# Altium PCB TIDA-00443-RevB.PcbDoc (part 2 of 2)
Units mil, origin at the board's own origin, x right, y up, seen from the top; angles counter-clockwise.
Board outline 5881 x 3685.61 mil, 2 copper layers (Top Layer, Bottom Layer), stack 62 mil thick; 123 components, 50 nets, 265 pads, 37 vias.
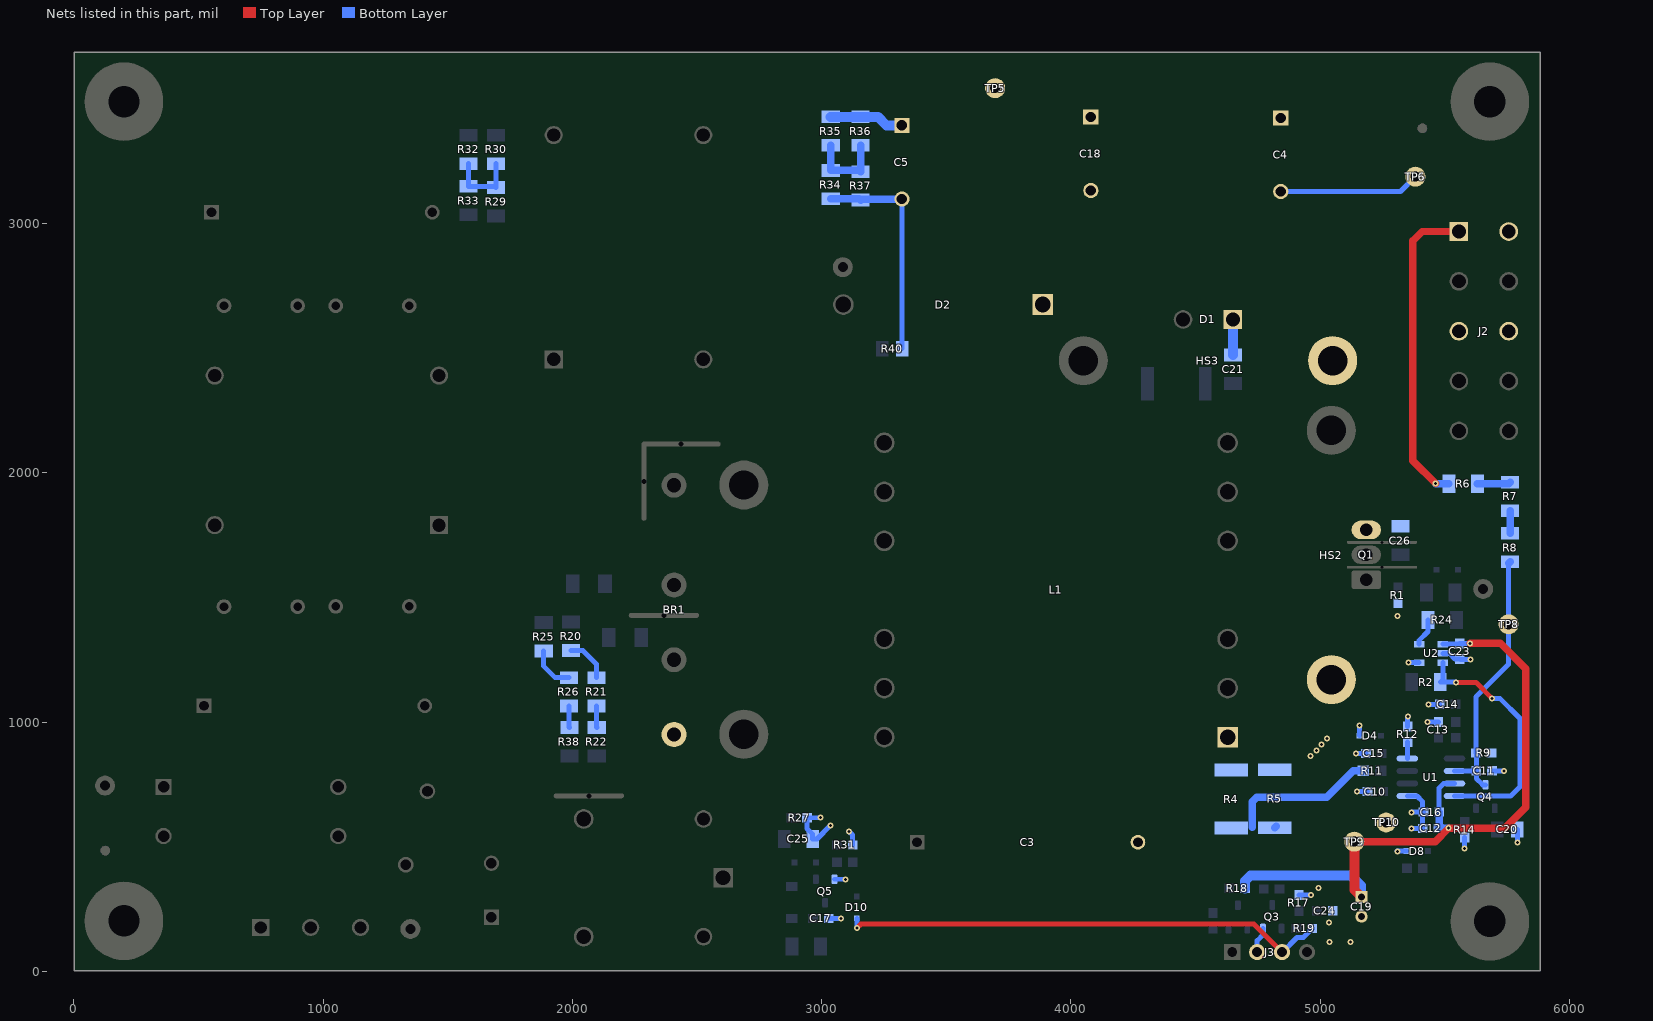
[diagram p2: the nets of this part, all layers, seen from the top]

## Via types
v1: diameter 24, hole 12, Top Layer to Bottom Layer, tented both sides, 37 vias

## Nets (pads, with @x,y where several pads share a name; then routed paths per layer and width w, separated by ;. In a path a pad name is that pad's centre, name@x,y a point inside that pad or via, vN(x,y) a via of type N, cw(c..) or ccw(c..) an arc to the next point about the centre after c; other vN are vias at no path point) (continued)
NetR2_1: R2.1 U1.8 U2.3 | length 1014
  Top Layer w20: v1(5545,1159) 5625,1159 v1(5689,1095)
  Bottom Layer w20: U2.3@5491.99,1237.98 5491.99,1169.89 R2.1@5482.08,1159.98 5544.02,1159.98 v1(5545,1159) ; U1.8@5538.99,703.5 5764.5,703.5 5802,741 5802,1014 5721,1095 v1(5689,1095)
NetR6_1: R6.1 R7.2 | length 133.4
  Bottom Layer w30: R6.1@5631.09,1956 5755.91,1956 R7.2@5762,1962.09
NetR7_1: R7.1 R8.2 | length 90.8
  Bottom Layer w30: R8.2@5762,1757.09 R7.1@5762,1847.91
NetR12_1: R12.1 U1.4 | length 66.4
  Bottom Layer w20: U1.4@5350.02,853.5 5350.02,918.51 R12.1@5350.99,919.48
NetR20_1: R20.1 R21.1 | length 178.7
  Bottom Layer w20: R20.1@1995,1286.91 2042.09,1286.91 2097,1232 R21.1@2097,1178.09
NetR21_2: R21.2 R22.2 | length 86.2
  Bottom Layer w20: R21.2@2097,1063.91 2097,979.09 R22.2@2098,978.09
NetR24_2: R24.2 U2.5 | length 111.9
  Bottom Layer w20: U2.5@5397.5,1312.78 5397.5,1327.5 5432.9,1362.9 R24.2@5432.9,1409.98
NetR25_1: R25.1 R26.1 | length 180.9
  Bottom Layer w20: R25.1@1885,1284.91 1885,1224 1930.91,1178.09 R26.1@1986,1178.09
NetR26_2: R26.2 R38.1 | length 86.7
  Bottom Layer w20: R26.2@1986,1063.91 1986,980.09 R38.1@1988,978.09
NetR29_1: R29.1 R30.2 R32.2 R33.1 | length 298.7
  Bottom Layer w20: R32.2@1583.64,3239.97 R33.1@1583.64,3149.14 1688.64,3149.14 R29.1@1693.64,3144.14 R30.2@1693.64,3239.97
NetR34_2: R34.2 R35.1 R36.1 R37.2 | length 328.7
  Bottom Layer w30: R35.1@3036.36,3313.97 R34.2@3036.36,3213.14 3151.36,3213.14 R37.2@3156.36,3208.14 R36.1@3156.36,3313.97
PFC_ON: D10.2 J3.3 R19.1 | length 1960.9
  Top Layer w20: v1(3141,173) 3158,190 4734,190 J3.3@4846.98,77.03
  Bottom Layer w20: v1(3141,173) D10.2@3141,212.69 ; J3.3@4846.98,77.03 4849,77.03 4907.27,135.3 4932.64,135.3 4968.5,171.15 R19.1@4968.5,172
PGND: C4.2 C5.2 C10.2 C11.2 C12.2 C13.1 C14.2 C15.1 C16.2 C17.2 C18.2 C19.2 C20.2 C23.2 C24.2 C25.2 C26.2 D4.2 D8.1 HS2.2 HS3.2 J2.3 J3.2 L1.1 Q1.3 Q3.2 Q5.2 R1.2 R4.1 R5.1 R9.1 R12.2 R14.2 R17.1 R27.1 R31.1 R34.1 R37.1 R40.1 TP6.1 TP10.1 U1.1 U2.2 U2.4 | length 2879.1
  Bottom Layer w20: v1(2995,617) 2994,616 R27.1@2941.5,616 2941.5,572.5 2964.09,549.91 C25.2@2964.09,531 2981,531 v1(3035,585) ; C17.2@3028.5,212 v1(3078,212) ; Q5.2@3051.4,369.24 3094.76,369.24 v1(3095,369) ; v1(3110,561) 3124.5,546.5 R31.1@3124.5,507 ; R37.1@3151.36,3098.97 R37.1@3156.36,3093.97 ; R40.1@3322,2498 C5.2@3322,3098.36 ; J3.2@4746.98,77.03 4746.98,122.98 4770.6,146.6 Q3.2@4770.6,171.76 ; C4.2@4842,3128.36 5322.36,3128.36 TP6.1@5382,3188 ; R17.1@4915,305.5 4963.5,305.5 v1(4964,306) ; v1(5143,874) 5147,874 C15.1@5183.49,873.98 ; v1(5148,722) 5150,722 5151.02,720.98 C10.2@5189.49,720.98 ; D4.2@5157.68,944.98 5157.68,985.68 v1(5158,986) ; v1(5310,481) 5309,482 D8.1@5346.69,482 ; U1.1@5350.02,703.5 5388.5,703.5 5411.5,680.5 C16.2@5411.5,639 ; R12.2@5350.99,982.47 5350.99,1021.99 v1(5352,1023) ; v1(5355,1238) 5360,1238 U2.4@5397.5,1237.98 ; v1@5365,573 v1(5366,573) C12.2@5411.5,573 C16.2@5411.5,639 ; v1(5367,638) 5368,639 C16.2@5411.5,639 ; C16.2@5414.5,639 C16.2@5411.5,639 ; v1(5431,1000) 5437,1000 C13.1@5474.5,999.99 ; v1(5434,1070) 5434.98,1070.98 C14.2@5479.49,1070.98 ; U2.2@5491.99,1275.38 5517.62,1275.38 5540.52,1252.48 C23.2@5559.99,1252.48 5562.49,1249.98 5596.98,1249.98 v1(5604,1250) ; v1(5579,492) 5580,492 R14.2@5580,536.5 ; C11.2@5689.5,804 v1(5737,804) ; v1(5791,517) C20.2@5791,569
  Bottom Layer w30: R34.1@3036.36,3098.97 R37.1@3151.36,3098.97 ; R37.1@3156.36,3093.97 3160.76,3098.36 C5.2@3322,3098.36
  other v1: 5037,118 5122,118 5036,195 4993,335 4962,864 4985,886 5006,909 5027,933 5310,1425
RTN: BR1.4 C3.2 R4.2 R5.2 R11.1 | length 606.8
  Bottom Layer w30: 4728,577 4728,681 4745,698 5026,698 5131.98,803.98 R11.1@5172.56,803.98 ; R5.2@4818,575.86 R5.2@4823.14,581
VCC: C12.1 C16.1 C19.1 C23.1 R18.2 TP9.1 U1.7 U2.1 | length 2756.3
  Top Layer w30: TP9.1@5137,520 5461,520 v1(5515,574) 5740,574 5825,659 5825,1214 5723.53,1315.47 v1(5601.47,1315.47)
  Top Layer w40: TP9.1@5137,520 5138,519 5138,326.37 C19.1@5166,298.37
  Bottom Layer w20: C16.1@5477.5,639 5477.5,735.5 5495.5,753.5 U1.7@5538.99,753.5 ; U2.1@5491.99,1312.78 5557.3,1312.78 C23.1@5559.99,1315.47 v1(5601.47,1315.47)
  Bottom Layer w30: C16.1@5477.5,639 5477.5,576 C12.1@5474.5,573 5514,573 v1(5515,574)
  Bottom Layer w40: R18.2@4698.5,333 4698.5,362.5 4720,384 5123,384 5163,344 5163,295.37 C19.1@5166,298.37
VDCBUS: C4.1 C5.1 C18.1 C21.1 D1.1 D2.1 J2.1 R6.2 R35.2 R36.2 TP5.1 | length 1713.3
  Top Layer w30: v1(5463,1957) 5372,2048 5372,2930 5410,2968 J2.1@5556.61,2968
  Bottom Layer w30: v1(5463,1957) 5464,1956 R6.2@5516.91,1956
  Bottom Layer w40: R35.2@3036.36,3428.14 R36.2@3156.36,3428.14 3225.86,3428.14 3260.36,3393.64 C5.1@3322,3393.64 ; D1.1@4650,2615 4651,2614 C21.1@4651,2472.09 ; J2.1@5553.29,2964.68 J2.1@5556.61,2968
VSENSE: C11.1 Q4.3 R8.1 R9.2 TP8.1 U1.6 | length 1070.4
  Bottom Layer w20: U1.6@5538.99,803.5 5626,803.5 C11.1@5626.5,804 ; Q4.3@5663,748.24 5651.76,748.24 5626.5,773.5 C11.1@5626.5,804 ; TP8.1@5756,1392 R8.1@5756,1636.91 ; TP8.1@5762,1398 5755,1391 5755,1231 5624.5,1100.5 R9.2@5624.5,876 5626.5,874 C11.1@5626.5,804
  Bottom Layer w30: R8.1@5756,1636.91 R8.1@5762,1642.91
pads on no net: FID1.1 FID2.1 FID3.1 FID4.1 H1.0 H2.0 H3.0 H4.0 H7.1 H8.1 H10.1 HS1.2 HS2.1 HS3.1 J2.2 J2.4 J2.5 K1.4 L1.7 L1.8 L1.9 L1.10 L1.11 L1.12

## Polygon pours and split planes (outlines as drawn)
NetC1_2 on Bottom Layer "Top Layer-No Net 5" (solid, remove dead copper, pour order 49): 2100,650 2100,575 2075,550 1750,550 1725,525 1725,400 1700,375 1650,375 1625,400 1625,896 1495,1026 1297,1026 1250,1073 1250,1825 1300,1875 1575,1875 1625,1825 1625,1200 1813,1012 1813,698 1836,675 2075,675
NetBR1_3 on Bottom Layer "Bottom Layer-No Net 2" (solid, remove dead copper, pour order 55): 2225,1207 2234,1198 3057,1198 3090,1226 3090,2185 2895,2380 2895,2660 2687,2867 2687,3463 2675,3475 2432,3475 2418,3461 2418,2868 2425,2850 2700,2575 2700,2250 2850,2100 2850,1410 2818,1378 2245,1378 2225,1358
NetC2_2 on Bottom Layer "Top Layer-No Net 8" (solid, remove dead copper, pour order 52): 1577,2298 1602,2323 1602,2848 1612,2858 1652,2858 1662,2848 1662,2407 1676,2393 1948,2393 1965,2410 1965,3053 1936,3082 1336,3082 1302,3048 1302,2323 1327,2298
PGND on Bottom Layer "Top Layer-No Net 2" (solid, pour order 32): 5099,1742 5106,1735 5381,1735 5391,1745 5391,1934 5374,1951 5110,1951 5099,1940
NetF1_1 on Bottom Layer "Top Layer-No Net" (solid, remove dead copper, pour order 44): 776,96 787,107 787,268.82 599,455.68 599,723 545,777 307,777 251,721 251,521 617,155 617,113 634,96
GNDE on Bottom Layer "Bottom Layer-No Net 3" (solid, remove dead copper, pour order 56): 925,125 984,125 994,135 994,385 900,479 900,805 1080,985 1080,3415 905,3590 90,3590 75,3575 75,3415 105,3385 830,3385 865,3350 865,1035 725,895 725,509 908,326 908,142
NetC1_1 on Bottom Layer "Top Layer-No Net 9" (solid, remove dead copper, pour order 57): 450,1900 649,1900 675,1874 675,980 459,980 425,1014 425,1875
NetC2_1 on Bottom Layer "Bottom Layer-No Net 5" (solid, remove dead copper, pour order 58): 455,2300 670,2300 695,2325 695,3220 670,3245 455,3245 430,3220 430,2325 455,2300
PGND on Bottom Layer "Bottom Layer-No Net 10" (solid, remove dead copper, pour order 39): 5374,1876 5390,1892 5390,2492 5400,2502 5808,2502 5820,2514 5820,2623 5809,2634 5361,2634 5334,2661 5334.01,3123.99 5194,3264 3315,3264 3261,3210 3261,2897 3286,2872 4771,2872 4817,2826 4817,1886 4827,1876
PGND on Bottom Layer "Bottom Layer-No Net 11" (solid, remove dead copper, pour order 40): 5245,1879 5245,1746 5232,1733 5104,1733 5096,1725 5096,1323.36 5147,1272 5147,1119 5072,1044 5072,920 4930,778 4578,778 4564,792 4564,974 4571,981 4789,981 4797,989 4797,1878 4817,1898 5226,1898
RTN on Bottom Layer "Bottom Layer-No Net 8" (solid, remove dead copper, pour order 36): 2342.95,884.88 2368.95,858.88 2432.95,858.88 2523.95,766.88 3523.95,766.88 3821.49,482 4892,482 4895,485 4895,657 4887,665 4364.83,665 3968.95,1060.88 2364.95,1060.88 2342.95,1038.88
NetJ1_3 on Bottom Layer "Top Layer-No Net 1" (solid, remove dead copper, pour order 46): 1106,231 1106,119 1125,100 1400,100 1425,125 1425,300 1430,305 1435,305 1439,301 1439,136 1475,100 1725,100 1935,310 2640,310 2650,320 2650,441 2641,450 1900,450 1750,300 1650,300 1440,510 1300,510 1283,493 1283,269 1264,250 1125,250
NetBR1_2 on Bottom Layer "Bottom Layer-No Net 1" (solid, remove dead copper, pour order 54): 2499,1599 2499,1499 2474,1474 2124,1474 2099,1499 2100,2300 2115,2315 2402,2315 2412,2325 2412,2516 2425,2529 2559,2529 2571,2517 2571,2191 2560,2180 2275,2180 2260,2165 2260,1638 2274,1624 2474,1624
PGND on Bottom Layer "Top Layer-No Net 6" (solid, remove dead copper, pour order 42): 5843,1590 5851,1582 5851,449 5789,387 5529,387 5415,273 5415,30 5402,17 5400,19 3010,20 2812,20 2765,126 2765,549.39 2848.06,636 3180,636 3195,621 3195,424 3275,344 3275,310.15 3275,298 3275,292 3284,283 3320,283 4536,281 4642,387 4901,387 4955,441 4955,739.89 4971,756 4971,769 4935,805 4935,821 5023,910 5037,910 5069,878 5076,878 5127,929 5127,1029 5271,1173 5271,1573 5288,1590
VDCBUS on Top Layer "Bottom Layer-No Net 12" (solid, remove dead copper, pour order 33): 3992,2621 3992,2869 3839,3022 3839,3121 3791,3169 3688,3169 3626,3107 3626,2945 3836,2735 3836,2619 3853,2602 3973,2602
PGND on Top Layer "Top Layer-No Net" (solid, remove dead copper, pour order 31): 2396,764 3166,764 3190,740 3190,370 3301.24,258.76 4856.24,258.76 4880,235 4880,50 4870,40 2825,40 2805,60 2805,695 2780,720 2400,720 2385,735 2385,753
PGND on Top Layer "Top Layer-No Net 6" (solid, remove dead copper, pour order 41): 5838,1610 5846,1602 5846,469 5784,407 5524,407 5410,293 5410,50 5397,37 5395,39 3430,45 3385,115 3315,155 3345,175 3285,230 3250,300 3355,300 4531,301 4636,406 4894,406 4950,462 4950,877 5266,1193 5266,1593 5283,1610
NetC1_2 on Top Layer "Top Layer-No Net 5" (solid, remove dead copper, pour order 48): 2100,650 2100,575 2075,550 1750,550 1725,525 1725,400 1700,375 1650,375 1625,400 1625,896 1495,1026 1297,1026 1250,1073 1250,1825 1300,1875 1575,1875 1625,1825 1625,1200 1814,1011 1814,697 1836,675 2075,675
NetC2_2 on Top Layer "Top Layer-No Net 8" (solid, remove dead copper, pour order 51): 1576,2298 1601,2323 1601,2848 1611,2858 1651,2858 1661,2848 1661,2407 1675,2393 1947,2393 1964,2410 1964,3053 1935,3082 1335,3082 1301,3048 1301,2323 1326,2298
NetBR1_2 on Top Layer "Bottom Layer-No Net 1" (solid, remove dead copper, pour order 53): 2498,1600 2498,1500 2473,1475 2123,1475 2098,1500 2099,2301 2114,2316 2401,2316 2411,2326 2411,2541 2421,2551 2564,2551 2570,2545 2570,2192 2559,2181 2274,2181 2259,2166 2259,1639 2273,1625 2473,1625
NetC26_1 on Top Layer "Bottom Layer-No Net 9" (solid, remove dead copper, pour order 38): 5245,1646 5232,1633 4614,1632 4516,1730 4516,2124 4405,2235 4405,2648 4416,2659 4474,2659 4486,2647 4486,2448 4525,2409 4526,2409 4730,2205 4730,1890 4911,1709 5233,1709 5245,1697
VDCBUS on Top Layer "Top Layer-No Net 2" (solid, pour order 30): 4599,2575 4610,2564 4692,2564 4702,2574 4702,2878 4697,2883 4603,2883 4599,2879
NetF1_1 on Top Layer "Top Layer-No Net" (solid, remove dead copper, pour order 43): 775,100 794,119 794,349 629,513 629,753 616,766 291,766 250,725 250,525 600,175 600,118 618,100
NetC1_1 on Top Layer "Top Layer-No Net 3" (solid, remove dead copper, pour order 47): 1475,664 1461,650 1170,650 1159,639 1159,495 1139,475 837,475 817,495 817,890 807,900 450,900 425,925 425,1200 425,1850 425,1874 425,1875 450,1900 650,1900 675,1875 675,1188 703,1160 995,1160 1025,1130 1025,910 1059,876 1294,876 1306,864 1306,772 1316,762 1463,762 1475,750
NetC2_1 on Top Layer "Top Layer-No Net 7" (solid, remove dead copper, pour order 50): 455,2300 670,2300 695,2325 695,3220 705,3230 2010,3230 2025,3245 2025,3455 2005,3475 575,3475 430,3330 430,2325
VDCBUS on Top Layer "Bottom Layer-No Net" (solid, remove dead copper, pour order 37): 4689,2865 4710,2886 4710,3215 4759,3264 4925,3264 4981,3208 4981,2958 5042,2897 5807,2897 5826,2916 5826,3044 5805,3065 5271,3065 5263,3073 5263,3575 5221,3617 3263,3617 3247,3601 3247,3280 3263,3264 3597,3264 3626,3235 3626,2959 3720,2865
NetJ1_3 on Top Layer "Top Layer-No Net 1" (solid, remove dead copper, pour order 45): 1106,231 1106,119 1125,100 1400,100 1425,125 1425,300 1430,305 1435,305 1439,301 1439,136 1475,100 1725,100 1935,310 2658.58,310 2675,326.42 2675,425 2650,450 1900,450 1750,300 1650,300 1440,510 1300,510 1283,493 1283,269 1264,250 1125,250
NetBR1_1 on Top Layer "Bottom Layer-No Net 6" (solid, remove dead copper, pour order 34): 2363,2018 2349,2004 2349,1858 2472,1735 2575,1735 2644,1666 2644,1575 2691,1528 3299,1528 3320,1507 3320,485 3329,476 3411,476 3424,489 3424,571 3628,775 3628,1782 3586,1824 2615,1824 2562,1877 2562,2001 2545,2018
NetBR1_1 on Top Layer "Top Layer-No Net 4" (solid, remove dead copper, pour order 35): 3332,489 3336,485 3824,485 4080,741 4080,1081 4093,1094 4659,1094 4682,1117 4682,1424 4668,1438 4020,1438 3789,1207 3789,816 3738,765 3656,765 3443,552 3340,552 3332,544

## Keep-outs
Top Layer:
  circle w6: c4080,3132.36 r110
Keep-Out Layer:
  lines w10: 21,22 21,3665 ; 24,22 5859,22 5859,3665 24,3665

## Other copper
Top Layer:
  text ".Layer_Name" at 505,-1086.49 h60
Bottom Layer:
  text ".Layer_Name" at 505,-1086.49 h60

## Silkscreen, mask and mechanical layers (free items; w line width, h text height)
Top Overlay:
  circle w6: c5281,1537 r6.4
  circle w6: c4684,2711 r6.4
  circle w6: c2354,2078 r6.4
  circle w6: c4771,921 r6.4
  lines w6: 2221,1957 2242,1957 ; 2231,1943 2231,1971 ; 2324,844 2324,2056 2544,2056 2544,844 2324,844
  text "TIDA-00443-RevB" at 583,3540 h60
  text ".Layer_Name" at 505,-1086.49 h60
Bottom Overlay:
  circle w6: c5504,1343 r7.81
  circle w6: c5308,677 r5.83
  lines w6: 3011,178 3011,172 3020,163 3029,163 ; 3080,332 3082,332 3100,350 3108,350 ; 5440,952 5420,952 5407,965 5407,1006 ; 5407,1006 5401,1000 5413,1000 5407,1006
  text "R9" at 5696,918 h30
  text ".Layer_Name" at 505,-1086.49 h60
Top Paste:
  text ".Layer_Name" at 505,-1086.49 h60
Bottom Paste:
  text ".Layer_Name" at 505,-1086.49 h60
Top Solder:
  text ".Layer_Name" at 505,-1086.49 h60
  text ".Layer_Name" at 505,-1086.49 h60
Bottom Solder:
  text ".Layer_Name" at 505,-1086.49 h60
Drill Guide:
  text ".Layer_Name" at 505,-1086.49 h60
M1 Board Outline:
  the board outline again, w10
M2 Board Dimensions:
  rectangle: -72,-503 53,-378
  rectangle: 53,-628 428,-503
  lines w7: -72,-503 928,-503 ; 53,-628 53,-378 ; 178,-628 178,-378 ; 428,-628 428,-378 ; 678,-628 678,-378 ; -72,-628 928,-628 928,-378 -72,-378 -72,-628
M3 3D STEP Top:
  text ".Layer_Name" at 505,-1086.49 h60
M4 3D STEP Bottom:
  text ".Layer_Name" at 505,-1086.49 h60
M5 Assembly Top:
  circle w6: c2683.8,366 r10.2
  circle w6: c2396,2033 r10.77
  circle w6: c4613,114 r7.62
  circle w6: c5216,1503 r12.81
  circle w6: c4724,2653 r8
  circle w10: c1529,1789 r14.32
  lines w10: -364,-1158.17 6236,-1158.17 ; -364,-954.83 6238,-954.83 ; -364,-751.5 -364,-1361.5 3641,-1361.5 6238,-1361.5 6238,-751.5 -363.5,-751.5 -363.5,-1361.5 1212,-1361.5 ; 2101,-1361.5 2101,-751.5 ; 3368,-954.83 3368,-751.5 ; 4208,-954.83 4208,-751.5 ; 4830,-1368 4830,-1165.17
  text "COMPONENTS MARKED 'DNP' SHOULD NOT BE POPULATED." at 1081.5,-546.5 h30
  text "ASSEMBLY VARIANT:" at 1081,-662 h30
  text ".VariantName" at 2117,-662 h30
  text "PCB VIEWED FROM TOP SIDE" at -300.5,-883.67 h30
  text "BOARD #:" at 2176,-883.67 h30
  text ".PRJ_Number" at 2721.5,-883.67 h30
  text "REV:" at 3566,-883.67 h30
  text ".PCB_Rev" at 3857.5,-883.67 h30
  text "SVN REV:" at 4404,-883.67 h30
  text ".VersionControl_RevNumber" at 4910,-883.67 h30
  text ".layer_Name" at 486,-1076 h60
  text "PLOT NAME =" at -300.5,-1292.34 h30
  text ".plot_File_Name" at 505,-1292.34 h30
  text "GENERATED    :" at 2178,-1292.34 h30
  text ".Print_Date" at 3047.5,-1292.34 h30
  text ".Print_Time" at 3776.5,-1292.34 h30
  text "TEXAS INSTRUMENTS" at 5041,-1292.34 h30
M6 Assembly Bottom:
  circle w6: c5459,1314 r5.66
  circle w6: c5382,704 r7.07
  circle w6: c5704.29,694 r7.71
  circle w6: c4847,209 r7.81
  circle w6: c4710,209 r7.21
  circle w6: c2976.49,381 r5.51
  lines w10: -364.5,-955.33 6237.5,-955.33 ; -362.5,-1158.67 6237.5,-1158.67 ; 1043.5,-1368.5 1043.5,-1165.67 ; 1665.5,-955.33 1665.5,-752 ; 2505.5,-955.33 2505.5,-752 ; 3772.5,-1362 3772.5,-752 ; 4661.5,-1362 6237,-1362 6237,-752 -364.5,-752 -364.5,-1362 2232.5,-1362 6237.5,-1362 6237.5,-752
  text "COMPONENTS MARKED 'DNP' SHOULD NOT BE POPULATED." at 6030,-546 h30
  text ".VariantName" at 4986,-662 h30
  text "ASSEMBLY VARIANT:" at 6025,-662 h30
  text ".VersionControl_RevNumber" at 963.5,-884.17 h30
  text "SVN REV:" at 1469.5,-884.17 h30
  text ".PCB_Rev" at 2016,-884.17 h30
  text "REV:" at 2307.5,-884.17 h30
  text ".PRJ_Number" at 3152,-884.17 h30
  text "BOARD #:" at 3697.5,-884.17 h30
  text "PCB VIEWED FROM BOTTOM SIDE" at 6174,-884.17 h30
  text ".layer_Name" at 5892,-1089 h60
  text "TEXAS INSTRUMENTS" at 832.5,-1292.84 h30
  text ".Print_Time" at 2097,-1292.84 h30
  text ".Print_Date" at 2826,-1292.84 h30
  text "GENERATED    :" at 3695.5,-1292.84 h30
  text ".plot_File_Name" at 5368.5,-1292.84 h30
  text "PLOT NAME =" at 6174,-1292.84 h30
M9 Title Sheet:
  drawing of 57 lines, arcs and shapes, not listed
  text "1" at 667.84,7808.5 h70
  text "2" at 3163.5,7808.5 h70
  text "3" at 5652.84,7808.5 h70
  text "4" at 8159.51,7808.5 h70
  text "5" at 10658.5,7808.5 h70
  text "6" at 13163.5,7808.5 h70
  text "A" at -488.5,6665.5 h70
  text "A" at 14311.5,6665.5 h70
  text "B" at -488.5,4285.5 h70
  text "B" at 14311.5,4285.5 h70
  text "C" at -488.5,1910.5 h70
  text "C" at 14311.5,1910.5 h70
  text "PROJECT TITLE:" at 11271.5,49.5 h45
  text ".PRJ_Title" at 11363,-81 h70
  text "DESIGNED FOR:" at 11271.5,-251.5 h45
  text ".PRJ_Customer" at 11321.5,-391.5 h70
  text "D" at -488.5,-459.5 h70
  text "D" at 14311.5,-459.5 h70
  text "FILE NAME:" at 11271.5,-551.5 h45
  text ".PCB_File_Name_No_Path" at 11321.5,-671.5 h70
  text "Texas Instruments (TI) and/or its licensors do not warrant the accuracy or completeness of this specification" at 6302,-833.34 h45
  text "ENGINEER:" at 11271.5,-841.5 h45
  text "LAYOUT BY:" at 12776.5,-841.5 h45
  text "or any information contained therein. TI and/or its licensors do not warrant that this design will meet" at 6257.01,-946 h45
  text ".PRJ_Engineer" at 11321.5,-996.49 h70
  text ".pcb_Layout" at 12827,-996.49 h70
  text "the specifications, will be suitable for your application or fit for any particular purpose, or will operate in" at 6257.01,-1058.67 h45
  text "ALTIUM DESIGNER VERSION:" at 12776.5,-1151.5 h45
  text "an implementation. TI and/or its licensors do not warrant that the design is production worthy. You should" at 6257.01,-1171.33 h45
  text "completely validate and test your design implementation to confirm the system functionality for your application." at 6302,-1284 h45
  text ".print_Scale" at 11321.5,-1284.83 h70
  text ".Application_BuildNumber" at 12827,-1284.83 h70
  text "1" at 667.84,-1491.5 h70
  text "2" at 3163.5,-1491.5 h70
  text "3" at 5652.84,-1491.5 h70
  text "4" at 8159.51,-1491.5 h70
  text "5" at 10658.5,-1491.5 h70
  text "6" at 13163.5,-1491.5 h70
M10 Fab Notes:
  drawing of 191 lines, arcs and shapes, not listed
  text "DESIGN INFORMATION" at 12315.02,6462 h60
  text "(REFER ALSO ARRAY/PANEL PROFILING INFORMATION)" at 11953.46,6300.29 h60
  text "BOARD SIZE" at 11267.46,6296 h60
  text "5881 MIL" at 11710,6170 h60
  text "X" at 12235.46,6168.18 h60
  text "3685.61 MIL" at 12429,6163 h60
  text "Number of Layers :" at 11685.46,6061 h60
  text "2" at 12780.27,6051 h60
  text "MIN. TRACK WIDTH:" at 11685.46,5922 h60
  text "MIL" at 12936.46,5922 h60
  text "20" at 12746,5920 h60
  text "MIN. CLEARANCE:" at 11685.46,5790 h60
  text "MIL" at 12936.46,5790 h60
  text "8" at 12773,5785 h60
  text "MIN. VIA PAD SIZE:" at 11685.46,5658 h60
  text "24" at 12748,5656 h60
  text "MIL" at 12933,5635 h60
  text "0.152mm (6MIL)" at 12380.46,5516.29 h60
  text "EXTERNAL" at 13131,5514 h60
  text "MINIMUM ANNULAR RING" at 11356.23,5512 h60
  text "PER" at 11556.23,5394 h60
  text "IPC-D-275 CLASS 2 LEVEL C" at 11776.23,5394 h60
  text "MIL, HOLES" at 13264.46,5281.71 h60
  text "+/-" at 12872,5281 h60
  text "+/-" at 13726,5281 h60
  text "REGISTRATION TOLERANCES:" at 11356.23,5276 h60
  text "METAL" at 12556,5276 h60
  text "5" at 13132.2,5276 h60
  text "3" at 13965.2,5276 h60
  text "MIL" at 14081.46,5276 h60
  text "IMPEDENCE CONTROLLED BOARD:NO" at 11389,5127 h60
  text "MATERIAL:" at 11265.46,4903.54 h60
  text "FR-4 High Tg" at 12251.9,4763.21 h60
  text "FR-408" at 11686.46,4754.64 h60
  text "OTHER" at 13174.46,4754.64 h60
  text "X" at 12090,4753 h60
  text "THICKNESS:" at 11267,4598 h60
  text "62.99 MIL (1.6mm) +/-10%" at 11926,4593 h60
  text "OTHER" at 13291.46,4587.64 h60
  text "X" at 11791,4585 h60
  text "TOLERANCE:" at 11340.23,4429.64 h60
  text "X" at 12179.53,4429.64 h60
  text "ANSI IPC-6012 TYPE 3 CLASS 2" at 12366.48,4429.64 h60
  text "OTHER +/-" at 12366.46,4273.64 h60
  text "BOW & TWIST:" at 11340.23,4116.64 h60
  text "X" at 12179.53,4116.64 h60
  text "ANSI IPC-6012 TYPE 3 CLASS 2" at 12366.48,4116.64 h60
  text "OTHER +/-" at 12366.46,3958.13 h60
  text "DRILLING:" at 11265.46,3819.64 h60
  text "REFERENCE:" at 11340.23,3702.64 h60
  text "X" at 11988.46,3702.64 h60
  text "AS SHOWN" at 12175.46,3702.64 h60
  text "X" at 12889.46,3702.64 h60
  text "NC_DRILL FILES" at 13026.46,3702.64 h60
  text "PTH MIN COPPER THICKNESS:" at 11340.23,3544.64 h60
  text "X" at 12690.46,3544.64 h60
  text "1MIL" at 12827.46,3544.64 h60
  text "OTHER" at 13324.46,3544.64 h60
  text "BOARD FINISH:" at 11265.46,3385.64 h60
  text "SILKSCREEN:" at 11420.68,3267.64 h60
  text "X" at 12369.46,3267.64 h60
  text "TOP" at 12495.46,3267.64 h60
  text "X" at 12879.46,3267.64 h60
  text "BOTTOM" at 13006.46,3267.64 h60
  text "SILKSCREEN COLOR:" at 11420.68,3100.64 h60
  text "X" at 12368.42,3100.64 h60
  text "WHITE" at 12495.46,3100.64 h60
  text "OTHER" at 13006.46,3100.64 h60
  text "SOLDER RESIST COLOR:" at 11420.68,2930.64 h60
  text "X" at 11988.42,2771.44 h60
  text "GREEN" at 12115.46,2771.44 h60
  text "BLUE" at 12706.46,2771.44 h60
  text "OTHER" at 13244.46,2771.44 h60
  text "IMMERSION GOLD (ENIG)" at 12326.46,2582.92 h60
  text "ENEPIG" at 13664,2579.64 h60
  text "SURFACE FINISH:" at 11265.46,2578.64 h60
  text "X" at 12139.51,2578.64 h60
  text "IMM. TIN/SILVER OR EQUIV" at 11595,2421.64 h60
  text "OTHER" at 13026.46,2421.64 h60
  text "ARRAY/PANEL:" at 11265.46,2242.64 h60
  text "CUT AND TRIM PER MECH LAYER 1" at 12326.46,2238.35 h60
  text "N.C. ROUTE" at 12326.46,2086.64 h60
  text "X" at 13005.46,2086.64 h60
  text "V. SCORE" at 13192.46,2086.64 h60
  text "CERTIFICATION:" at 11265.46,1949.64 h60
  text "MATERIALS AND WORKMANSHIP FOR ALL PCBS" at 11990.46,1949.64 h60
  text "TO MEET OR EXCEED THE REQUIREMENTS OF:" at 11990.46,1851.64 h60
  text "X" at 11616.96,1715.13 h60
  text "ANSI IPC-A-600F CLASS ->" at 11755.96,1715.13 h60
  text "X" at 13395.02,1715.13 h60
  text "2" at 13513.96,1715.14 h60
  text "1" at 13198.96,1713.64 h60
  text "3" at 13867.96,1713.64 h60
  text "X" at 11619.02,1555.64 h60
  text "UL 94V-0" at 11755.96,1555.64 h60
  text "X" at 12431.02,1555.64 h60
  text "RoHS" at 12567.96,1555.64 h60
  text "OTHER" at 13212.36,1555.64 h60
  text "PER ORDER" at 13609.42,1555.64 h60
  text "ADDITIONAL REQUIREMENTS:" at 11265.46,1414.64 h60
  text "MICROSECTION:" at 11340.23,1299.64 h60
  text "YES" at 12245.96,1299.64 h60
  text "REQUIRED" at 13107.46,1143.49 h60
  text "BARE BOARD ELEC. TEST:" at 11340.23,1140.64 h60
  text "NONE" at 12645.96,1140.64 h60
  text "X" at 12980.46,1140.64 h60
  text "PER ORDER" at 13699.46,1140.64 h60
  text "MANUFACTURER'S UL:" at 11340.23,983.64 h60
  text "RAIL" at 12505.96,979.35 h60
  text "METAL" at 12997.77,979.35 h60
  text "X" at 13373,979 h60
  text "SILK" at 13509.46,979.35 h60
  text "VIA`S TO BE TENTED:" at 11320,792 h60
  text "YES" at 12225,792 h60
M11 Gerber Information:
  lines w10: -364,-1158.17 6236,-1158.17 ; -364,-954.83 6238,-954.83 ; -364,-751.5 -364,-1361.5 3641,-1361.5 6238,-1361.5 6238,-751.5 -363.5,-751.5 -363.5,-1361.5 1212,-1361.5 ; 2101,-1361.5 2101,-751.5 ; 3368,-954.83 3368,-751.5 ; 4208,-954.83 4208,-751.5 ; 4830,-1368 4830,-1165.17
  text "ALL ARTWORK VIEWED FROM TOP SIDE" at -300.5,-883.67 h60
  text "BOARD #:" at 2176,-883.67 h60
  text ".PRJ_Number" at 2678,-883.67 h60
  text "REV:" at 3566,-883.67 h60
  text ".PCB_Rev" at 3857.5,-883.67 h60
  text "SVN REV:" at 4404,-883.67 h60
  text ".VersionControl_RevNumber" at 4910,-883.67 h60
  text "LAYER NAME =" at -300.5,-1086.49 h60
  text "PLOT NAME =" at -300.5,-1292.34 h60
  text ".plot_File_Name" at 505,-1292.34 h60
  text "GENERATED    :" at 2178,-1292.34 h60
  text ".Print_Date" at 3047.5,-1292.34 h60
  text ".Print_Time" at 3776.5,-1292.34 h60
  text "TEXAS INSTRUMENTS" at 5041,-1292.34 h60
M12 Stackup:
  lines w5: 11199,7429 14201,7428.12 ; 11200,7326 14201,7328.89 ; 11197,6635 ccw(c11229,6635) 11229,6603 14169,6603 ccw(c14169,6635) 14201,6635 14201,7656 ccw(c14169,7656) 14169,7688 11229,7688 ccw(c11229,7656) 11197,7656 11197,6635
  text "Layer Stack Up Detail for: TIDA-00443-RevB" at 11257,7521.37 h49
  text "Layer" at 11257,7391.13 h23
  text "Gerber" at 11875.49,7391.13 h23
  text "Copper" at 12187.42,7391.13 h23
  text "Dielectric" at 12536.89,7391.13 h23
  text "Dielectric" at 12902.47,7391.13 h23
  text "Dielectric" at 13361.01,7391.13 h23
  text "Dielectric" at 13726.58,7391.13 h23
  text "Name" at 11257,7345.13 h23
  text "Document" at 11875.49,7345.13 h23
  text "Thickness" at 12187.42,7345.13 h23
  text "Height" at 12536.89,7345.13 h23
  text "Material" at 12902.47,7345.13 h23
  text "Constant" at 13361.01,7345.13 h23
  text "Type" at 13726.58,7345.13 h23
  text "Top Solder Mask" at 11257,7258.52 h32
  text "(.GTS)" at 11875.49,7258.52 h32
  text "0.4mil" at 12536.89,7258.52 h32
  text "Solder Resist" at 12902.47,7258.52 h32
  text "3.50" at 13361.01,7258.52 h32
  text "Top Layer" at 11257,7122.9 h32
  text "(.GTL)" at 11875.49,7122.9 h32
  text "1.4mil" at 12187.42,7122.9 h32
  text "59.2mil" at 12536.89,7055.08 h32
  text "FR-4 High Tg" at 12902.47,7055.08 h32
  text "4.80" at 13361.01,7055.08 h32
  text "Core" at 13726.58,7055.08 h32
  text "Bottom Layer" at 11257,6987.27 h32
  text "(.GBL)" at 11875.49,6987.27 h32
  text "1.4mil" at 12187.42,6987.27 h32
  text "Bottom Solder Mask" at 11257,6851.65 h32
  text "(.GBS)" at 11875.49,6851.65 h32
  text "0.4mil" at 12536.89,6851.65 h32
  text "Solder Resist" at 12902.47,6851.65 h32
  text "3.50" at 13361.01,6851.65 h32
M13 Component Bodies Top:
  text ".Layer_Name" at 505,-1086.49 h60
M14 Component Bodies Bottom:
  text ".Layer_Name" at 505,-1086.49 h60
M15 Courtyards Top:
  text ".Layer_Name" at 505,-1086.49 h60
M16 Courtyards Bottom:
  text ".Layer_Name" at 505,-1086.49 h60
Drill Drawing:
  text ".legend" at 429.04,4390.39 h60
  text "Drill Table" at 439.04,4220.39 h60
  text "DRILL TOLERANCE" at 433.75,4106.92 h60
  text "FOR PTH +/- 3MIL" at 434.18,3997.48 h60
  text "12mil drill:+0/-12mil" at 429.04,3875.39 h60
  text "FOR NPTH +/- 2MIL" at 434,3775 h60
  text ".Layer_Name" at 505,-1086.49 h60

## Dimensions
5882,3687.61 to 5882,2 on M2 Board Dimensions
5882,2 to 1,2 on M2 Board Dimensions
-72,-628 to 928,-628 on M2 Board Dimensions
